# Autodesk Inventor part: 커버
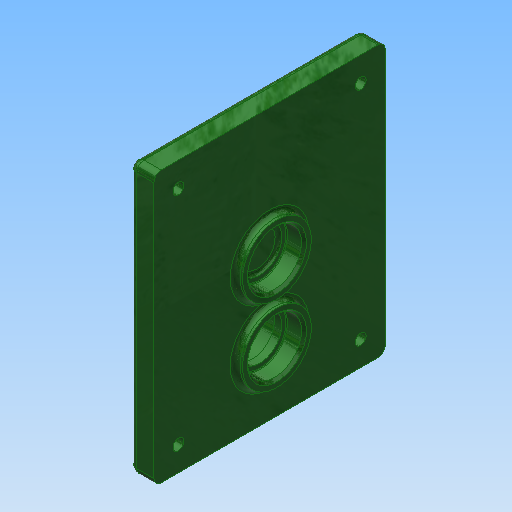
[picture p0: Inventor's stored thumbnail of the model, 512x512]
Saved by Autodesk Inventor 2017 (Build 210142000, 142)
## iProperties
Created: 2016-02
Part Number: 커버
Material: 알루미늄 6061
Document SubType Name: Modeling
Designer: mduedu
Density: 2.71 g/cm^3
Appearance: 매끄러움 - 짙은 산림 녹색
Mass: 271.622 g
Surface Area: 265.357 cm^2
Volume: 100.23 cm^3
Author: mduedu
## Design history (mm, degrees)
sketch "스케치1"
  geometry: L1 (63, 47)-(-47, 47); L2 (-47, 47)-(-47, -47); L3 (-47, -47)-(63, -47); L4 (63, -47)-(63, 47); 2 further points
  constraints: 8 end point, 2 parallel, 1 horizontal, 1 horizontal alignment, 1 midpoint, 1 perpendicular
  dimensions: "d102" = 94 distance of L3.end L1.start; "d104" = 47 distance from line of L2 point (0, 0); "d105" = 110 distance of L1.start L1.end
extrude "돌출1" new body sketch "스케치1" distance "d1" = 10; taper "d2" = 0 deg
sketch "스케치2"
  geometry: C1 r 14 at (0, 11); 1 further point
  constraints: 1 centre point, 1 vertical alignment
  dimensions: "d3" = 28 diameter of C1; "d6" = 11 distance of C1.centre point (0, 0)
extrude "돌출2" join sketch "스케치2" distance "d7" = 3; taper "d8" = 0 deg
sketch "스케치3"
  geometry: C1 r 14 at (0, -20); 1 further point
  constraints: 1 centre point, 1 vertical alignment
  dimensions: "d9" = 28 diameter of C1; "d10" = 20 distance of C1.centre point (0, 0)
extrude "돌출3" join sketch "스케치3" distance "d11" = 3; taper "d12" = 0 deg
hole "구멍1" diameter "d15" = 22; stored, may be unused: countersink angle "d19" = 90 deg, drill point angle "d21" = 0 deg; dims "d13" = 10, "d14" = 10, "d16" = 6, "d17" = 4, "d18" = 2, "d20" = 7
hole "구멍2" diameter "d24" = 18; stored, may be unused: countersink angle "d28" = 90 deg, drill point angle "d30" = 0 deg; dims "d22" = 10, "d23" = 10, "d25" = 6, "d26" = 4, "d27" = 2, "d29" = 1
hole "구멍3" diameter "d33" = 22; stored, may be unused: countersink angle "d37" = 90 deg, drill point angle "d39" = 0 deg; dims "d34" = 6, "d35" = 4, "d36" = 2, "d38" = 7, "d73" = 10, "d74" = 10
sketch "스케치4"
  geometry: C1 r 14 at (0, -20) reference; C2 r 18 at (0, -20); 1 further point
  constraints: 1 centre point, 1 coincident
  dimensions: "d40" = 36 diameter of C2
extrude "돌출4" join sketch "스케치4" distance "d41" = 4; taper "d42" = 0 deg
hole "구멍4" diameter "d45" = 22; stored, may be unused: countersink angle "d49" = 90 deg, drill point angle "d51" = 0 deg; dims "d43" = 10, "d44" = 10, "d46" = 6, "d47" = 4, "d48" = 2, "d50" = 7
hole "구멍5" diameter "d54" = 18; stored, may be unused: countersink angle "d58" = 90 deg, drill point angle "d60" = 0 deg; dims "d55" = 6, "d56" = 4, "d57" = 2, "d59" = 7, "d116" = 10, "d117" = 10
fillet "모깎기1" dims "d61" = 0.3
fillet "모깎기2" dims "d62" = 2
chamfer "모따기1" distance "d63" = 1; stored, may be unused: second distance "d64" = 2, angle "d65" = 45 deg
fillet "모깎기6" dims "d88" = 2
fillet "모깎기4" dims "d75" = 2
sketch "스케치9"
  geometry: L1 (47, 63)-(47, -47) reference; L2 (-47, 63)-(47, 63) reference; L3 (-47, -47)-(-47, 63) reference; L4 (47, -47)-(-47, -47) reference; L5 (37, 53)-(37, -37); L6 (37, -37)-(-37, -37); L7 (-37, -37)-(-37, 53); L8 (-37, 53)-(37, 53); C1 r 20 at (0, -20) reference; 5 further points
  constraints: 8 end point, 4 coincident, 3 other
  dimensions: "d107" = 10 distance between parallel lines of L8 L2
hole "구멍7" sketch "스케치9" at (-37, 53), (37, 53), (37, -37), (-37, -37) diameter "d108" = 4.5; stored, may be unused: countersink angle "d112" = 90 deg, drill point angle "d114" = 118 deg; dims "d109" = 6, "d110" = 8, "d111" = 4.6, "d113" = 8
fillet "모깎기8" dims "d106" = 3
fillet "모깎기9" dims "d115" = 3
node "솔리드1"
node "투영된 루프2"
